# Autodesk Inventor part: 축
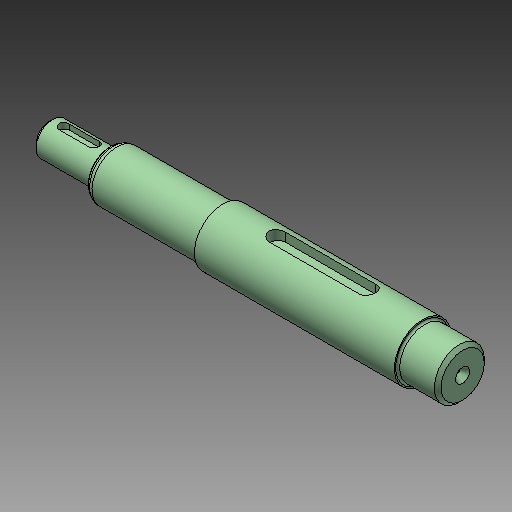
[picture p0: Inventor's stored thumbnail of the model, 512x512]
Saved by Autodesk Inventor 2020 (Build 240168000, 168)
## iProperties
Created: 2024-01
Part Number: 축
Material: 강철, 탄소
Document SubType Name: Modeling
Designer: mdu-01
Density: 1 g/cm^3
Appearance: 기본값(1)
Author: mdu-01
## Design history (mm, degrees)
sketch "스케치1"
  geometry: L1 (0, 0)-(118.751, 0); L2 (124, 2.125)-(124, 6.5); L3 (123, 7.5)-(112.6, 7.5); L4 (112, 8.1)-(112, 8.5); L5 (112, 8.5)-(52, 8.5); L6 (52, 8.5)-(52, 8.1); L7 (51.4, 7.5)-(20.268, 7.5); L8 (18, 5.923)-(18, 5); L9 (18, 5)-(1, 5); L10 (0, 4)-(0, 0); L11 (124, 2.125)-(122.051, 1); L12 (122.051, 1)-(119.329, 1); L13 (119.329, 1)-(118.751, 0); L14 (124, 6.5)-(123, 7.5); L15 (1, 5)-(0, 4); L16 (18.5, 6.789)-(19.268, 7.232); A1 r 0.6 centre (51.4, 8.1) between (51.4, 7.5) and (52, 8.1); A2 r 0.6 centre (112.6, 8.1) between (112, 8.1) and (112.6, 7.5); A3 r 2 centre (20.268, 5.5) between (20.268, 7.5) and (19.268, 7.232); A4 r 1 centre (19, 5.923) between (18.5, 6.789) and (18, 5.923); 3 further points
  constraints: 32 end point, 8 parallel, 8 point on circle, 8 tangent, 6 point on line, 4 centre point, 2 horizontal, 1 collinear, 1 equal radius, 1 perpendicular
  dimensions: "d0" = 2 diameter of L12 L1; "d2" = 4.25 diameter of L2.start L1; "d3" = 30 deg angle of L1 L11; "d4" = 60 deg angle of L1 L13; "d5" = 3.3 horizontal distance of L1.end L11.end; "d6" = 124 distance between parallel lines of L10 L2; "d7" = 12 distance between parallel lines of L4 L2; "d8" = 34 distance between parallel lines of L6 L8; "d9" = 18 distance between parallel lines of L8 L10; "d10" = 10 diameter of L9 L1; "d11" = 15 diameter of L7 L1; "d12" = 17 diameter of L5 L1; "d13" = 0.6 radius of A1; "d14" = 1 distance of L2.end point (124, 7.5); "d15" = 1 distance of L3.start point (124, 7.5) (= d14); "d16" = 1 distance of L9.end point (0, 5) (= d14); "d17" = 1 distance of L10.start point (0, 5) (= d16); "d18" = 13 diameter of point (18, 6.5) L1; "d19" = 30 deg angle of L7 L16; "d20" = 2 radius of A3; "d21" = 1 radius of A4
revolve "회전1" sketch "스케치1" stored, may be unused: angle "d22" = 90 deg
hole "구멍1" diameter "d25" = 3.242; stored, may be unused: countersink angle "d29" = 90 deg, drill point angle "d31" = 118 deg; dims "d23" = 10, "d24" = 10, "d26" = 8, "d27" = 4, "d28" = 2, "d30" = 10
sketch "스케치2"
  geometry: L1 (0, -1.621)-(0, 1.621) reference; L2 (0, -4)-(0, 4) reference; L3 (0, 0)-(4.59, 0); L4 (4.59, 0)-(0, 2.65); L5 (0, 2.65)-(0, 0)
  constraints: 6 end point, 1 collinear, 1 perpendicular, 1 point on line
  dimensions: "d32" = 30 deg angle of L3 L4; "d33" = 5.3 diameter of L4.end L3
revolve "회전2" sketch "스케치2" stored, may be unused: angle "d35" = 90 deg
sketch "스케치3"
  geometry: L1 (18, -5)-(18, 5) reference; L2 (1, -5)-(1, 5) reference; L3 (3, 5)-(15, 5); L4 (15, 5)-(15, 3.2); L5 (15, 3.2)-(3, 3.2); L6 (3, 3.2)-(3, 5); 1 further point
  constraints: 8 end point, 2 parallel, 1 horizontal, 1 perpendicular, 1 point on line
  dimensions: "d36" = 3 distance between parallel lines of L4 L1; "d37" = 12 distance between parallel lines of L6 L4; "d38" = 1.8 distance between parallel lines of L5 L3
extrude "돌출1" cut sketch "스케치3" stored distance "d39" = 3; taper "d40" = 0 deg
fillet "모깎기1"
fillet "모깎기2"
sketch "스케치4"
  geometry: L1 (112, -8.5)-(112, 8.5) reference; L2 (52, -8.5)-(52, 8.5) reference; L3 (66, 8.5)-(98, 8.5); L4 (98, 8.5)-(98, 5.5); L5 (98, 5.5)-(66, 5.5); L6 (66, 5.5)-(66, 8.5); 1 further point
  constraints: 8 end point, 2 parallel, 1 horizontal, 1 perpendicular, 1 point on line
  dimensions: "d41" = 14 distance between parallel lines of L6 L2; "d42" = 32 distance between parallel lines of L4 L6; "d43" = 3 distance between parallel lines of L5 L3
extrude "돌출2" cut sketch "스케치4" stored distance "d44" = 5; taper "d45" = 0 deg
fillet "모깎기3"
fillet "모깎기4"
node "솔리드1"
node "투영된 루프1"
node "투영된 루프2"
node "투영된 루프3"
